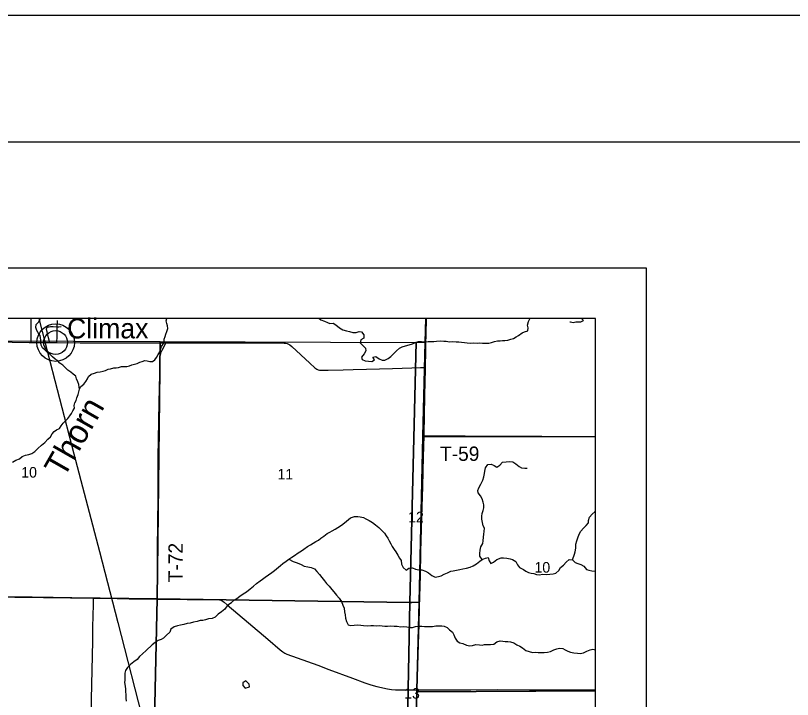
# Model space of a CAD drawing. Extents: x 0 to 34, y 0 to 22.
# Drawn here: x 6.5 to 9.58, y 19.29 to 22 of the extents above; entities that cross this region are included whole.
import ezdxf

# ---------------------------------------------------------------- set-up
doc = ezdxf.new("R2010")
doc.units = 0
for name, color, linetype in [('Default', 7, 'Continuous'), ('GM_X_City_Street', 7, 'Continuous'), ('GM_X_Corporation', 7, 'Continuous'), ('GM_X_County_Road_Text', 7, 'Continuous'), ('GM_X_Interchange_Ramps', 7, 'Continuous'), ('GM_X_Major_River', 7, 'Continuous'), ('GM_X_Major_River_Text', 7, 'Continuous'), ('GM_X_Minor_Lake', 7, 'Continuous'), ('GM_X_Minor_River', 7, 'Continuous'), ('GM_X_Section', 7, 'Continuous'), ('GM_X_Township_Text', 7, 'Continuous'), ('GM_X_Unincorporated_Location', 7, 'Continuous'), ('GM_X_Unincorporated_Text', 7, 'Continuous'), ('SH_Cut_Line', 7, 'Continuous'), ('SH_Data', 7, 'Continuous'), ('SH_Text', 7, 'Continuous')]:
    doc.layers.add(name, color=color, linetype=linetype)

msp = doc.modelspace()

# ---------------------------------------------------------------- linework, layer by layer
at = {"layer": 'Default'}
for points in [[(8.0903, 19.2721), (8.0916, 19.3249), (8.0917, 19.3288), (8.0943, 19.4242), (8.0975, 19.5485), (8.0985, 19.5857), (8.1001, 19.654), (8.1038, 19.7814), (8.1063, 19.8745), (8.111, 20.0547), (8.1134, 20.1323), (8.115, 20.1944), (8.1164, 20.2503), (8.1187, 20.3345), (8.1204, 20.4211), (8.1217, 20.4864), (8.1232, 20.5547), (8.124, 20.5889), (8.1241, 20.6054), (8.1242, 20.623), (8.1249, 20.654), (8.1259, 20.6975), (8.1269, 20.7379), (8.1282, 20.8), (2.9842, 20.8)], [(8.8, 18.8069), (8.8, 20.8), (8.1282, 20.8), (8.1269, 20.7379), (8.1259, 20.6975), (8.1249, 20.654), (8.1242, 20.623), (8.1241, 20.6054), (8.124, 20.5889), (8.1232, 20.5547), (8.1217, 20.4864), (8.1204, 20.4211), (8.1187, 20.3345), (8.1164, 20.2503), (8.115, 20.1944), (8.1134, 20.1323), (8.111, 20.0547), (8.1063, 19.8745), (8.1038, 19.7814), (8.1001, 19.654), (8.0985, 19.5857), (8.0975, 19.5485), (8.0943, 19.4242), (8.0917, 19.3288), (8.0916, 19.3249), (8.0903, 19.2721)]]:
    msp.add_lwpolyline(points, dxfattribs=at)
for points in [[(8.8, 20.3309), (8.8, 20.8), (8.1254, 20.8), (8.1235, 20.706), (8.1135, 20.3325)], [(8.8, 19.3242), (8.8, 20.3309), (8.1135, 20.3325), (8.099, 19.6752), (8.0902, 19.3206)], [(8.8, 18.3267), (8.8, 19.3242), (8.0902, 19.3206), (8.0725, 18.6456), (8.0624, 18.3353)]]:
    msp.add_lwpolyline(points, close=True, dxfattribs=at)
at = {"layer": 'GM_X_City_Street'}
msp.add_line((6.6358, 20.7044), (6.6643, 20.7042), dxfattribs=at)
for points in [[(8.1243, 20.6048), (8.1244, 20.6225), (8.1252, 20.6535), (8.1261, 20.697), (8.1271, 20.7373), (8.1284, 20.8)], [(6.0415, 20.7139), (6.0915, 20.7133), (6.2065, 20.7107), (6.4178, 20.7065), (6.5545, 20.704), (6.5629, 20.7041)], [(6.5629, 20.7041), (6.6135, 20.7045), (6.6358, 20.7044)], [(6.6643, 20.7042), (6.7565, 20.7036), (6.8839, 20.7035), (6.9772, 20.7033), (7.0704, 20.7033), (7.096, 20.7033)], [(7.096, 20.7033), (7.1916, 20.7032), (7.3004, 20.7028), (7.4029, 20.7027), (7.4868, 20.7025), (7.5646, 20.7024), (7.5709, 20.7018), (7.577, 20.7004), (7.5829, 20.698), (7.5883, 20.6947), (7.5956, 20.6887), (7.6663, 20.6231), (7.6869, 20.6043), (7.6944, 20.599), (7.6998, 20.5965), (7.7057, 20.595), (7.7148, 20.5941), (7.7396, 20.5945), (7.7986, 20.5964), (7.8389, 20.5977), (7.8917, 20.599), (7.9942, 20.6018), (8.0719, 20.6042), (8.1061, 20.6049), (8.1154, 20.6049), (8.1243, 20.6048)], [(8.1189, 20.3339), (8.1206, 20.4206), (8.1219, 20.4858), (8.1234, 20.5542), (8.1242, 20.5883), (8.1243, 20.6048)], [(8.0919, 19.3282), (8.0945, 19.4237), (8.0977, 19.5479), (8.0987, 19.5852), (8.1003, 19.6535), (8.1041, 19.7808), (8.1066, 19.874), (8.1112, 20.0541), (8.1136, 20.1317), (8.1152, 20.1939), (8.1166, 20.2498), (8.1189, 20.3339)], [(6.0463, 19.7017), (6.0657, 19.7015), (6.2459, 19.6996), (6.4137, 19.6984), (6.5194, 19.697), (6.5659, 19.6962), (6.6498, 19.6948), (6.7181, 19.6932), (6.8087, 19.6918)], [(6.8087, 19.6918), (6.8548, 19.6909), (6.9511, 19.6892), (7.0101, 19.6884), (7.0625, 19.6878)], [(7.0625, 19.6878), (7.1034, 19.6873), (7.181, 19.6865), (7.2991, 19.6854), (7.3083, 19.6847), (7.3141, 19.6833), (7.3196, 19.6808), (7.3271, 19.6755), (7.3387, 19.6653), (7.4242, 19.5931), (7.5002, 19.529), (7.5498, 19.4865), (7.5595, 19.4787), (7.5675, 19.4737), (7.576, 19.4698), (7.6988, 19.4253), (7.7425, 19.4091), (7.8355, 19.3741), (7.885, 19.3556), (7.9087, 19.3478), (7.9327, 19.3414), (7.9752, 19.3316), (7.9906, 19.3291), (8.0061, 19.328), (8.0496, 19.3278), (8.0919, 19.3282)], [(8.0736, 18.6435), (8.0739, 18.6535), (8.0751, 18.7032), (8.0778, 18.8047), (8.0814, 18.9392), (8.0833, 19.0138), (8.0854, 19.0883), (8.087, 19.1441), (8.0874, 19.1566), (8.0905, 19.2715), (8.0918, 19.3243), (8.0919, 19.3282)], [(8.0919, 19.3282), (8.1033, 19.3282), (8.2276, 19.3285), (8.3052, 19.3286), (8.4109, 19.3288), (8.5382, 19.3286), (8.591, 19.3285), (8.6811, 19.3279), (8.7371, 19.3285), (8.7836, 19.3286), (8.8, 19.3287)]]:
    msp.add_lwpolyline(points, dxfattribs=at)
at = {"layer": 'GM_X_Corporation'}
msp.add_lwpolyline([(6.5927, 20.8), (6.6173, 20.7022), (6.732, 20.2629), (6.8332, 19.8757), (6.9052, 19.5948), (7.0125, 19.1776), (7.1431, 18.6694), (7.2218, 18.3603), (7.335, 17.9018), (7.5012, 17.2442), (7.5672, 16.9911), (7.6376, 16.714), (7.7025, 16.4605), (7.7388, 16.3223), (7.7626, 16.2427), (7.7756, 16.2117), (7.8081, 16.1506), (7.8441, 16.0969), (7.8846, 16.0477), (7.9314, 15.9998), (7.9673, 15.9687)], dxfattribs=at)
at = {"layer": 'GM_X_Interchange_Ramps'}
for points in [[(6.5629, 20.7041), (6.5628, 20.7107), (6.5625, 20.7261), (6.5623, 20.7416), (6.5624, 20.757), (6.5626, 20.7662), (6.5627, 20.7754), (6.5624, 20.7908), (6.5624, 20.8)], [(6.6652, 20.7663), (6.6656, 20.7715), (6.6665, 20.7832), (6.6671, 20.7919)], [(6.6358, 20.7044), (6.6352, 20.7067), (6.6331, 20.7142), (6.6307, 20.7225), (6.6264, 20.7407), (6.6253, 20.7471), (6.6236, 20.7557), (6.6235, 20.7575), (6.6236, 20.7591), (6.6238, 20.7606), (6.6243, 20.7622), (6.626, 20.7645)], [(6.626, 20.7645), (6.6276, 20.7657), (6.6293, 20.7664), (6.6306, 20.7667), (6.6337, 20.7671), (6.6388, 20.7675), (6.6428, 20.7677), (6.6492, 20.7675), (6.6652, 20.7663)], [(6.6643, 20.7042), (6.6644, 20.7066), (6.6651, 20.7254), (6.6651, 20.7317), (6.6648, 20.7467), (6.6649, 20.7558), (6.6652, 20.7663)], [(6.6652, 20.7663), (6.6721, 20.7668), (6.6815, 20.7672)], [(7.0625, 19.6878), (7.0626, 19.6955), (7.0634, 19.8258), (7.0637, 19.8972), (7.0642, 19.9748), (7.0653, 20.102), (7.0663, 20.251), (7.0674, 20.3192), (7.0702, 20.468), (7.0713, 20.5208), (7.0732, 20.6387), (7.0742, 20.6511), (7.076, 20.6602), (7.0779, 20.6661), (7.0818, 20.6745), (7.0909, 20.6907), (7.092, 20.6936), (7.096, 20.7033)], [(8.1189, 20.3339), (8.127, 20.3339), (8.2016, 20.334), (8.2824, 20.334), (8.3352, 20.3338), (8.4253, 20.3334), (8.5434, 20.333), (8.5869, 20.3329), (8.708, 20.3321), (8.8, 20.3317)], [(6.0463, 19.7017), (6.0657, 19.7015), (6.2459, 19.6996), (6.4137, 19.6984), (6.5194, 19.697), (6.5659, 19.6962), (6.6498, 19.6948), (6.7181, 19.6932), (6.8087, 19.6918)], [(6.7887, 18.6761), (6.7888, 18.6826), (6.7928, 18.872), (6.7948, 18.9558), (6.7982, 19.1297), (6.801, 19.2911), (6.8063, 19.5209), (6.8072, 19.5737), (6.8083, 19.6234), (6.8088, 19.6637), (6.8087, 19.6824), (6.8087, 19.6918)], [(6.8087, 19.6918), (6.8548, 19.6909), (6.9511, 19.6892), (7.0101, 19.6884), (7.0625, 19.6878)], [(7.0625, 19.6878), (7.1034, 19.6873), (7.181, 19.6865), (7.2991, 19.6854), (7.3083, 19.6847), (7.3141, 19.6833), (7.3196, 19.6808), (7.3271, 19.6755), (7.3387, 19.6653), (7.4242, 19.5931), (7.5002, 19.529), (7.5498, 19.4865), (7.5595, 19.4787), (7.5675, 19.4737), (7.576, 19.4698), (7.6988, 19.4253), (7.7425, 19.4091), (7.8355, 19.3741), (7.885, 19.3556), (7.9087, 19.3478), (7.9327, 19.3414), (7.9752, 19.3316), (7.9906, 19.3291), (8.0061, 19.328), (8.0496, 19.3278), (8.0919, 19.3282)], [(8.0919, 19.3282), (8.1033, 19.3282), (8.2276, 19.3285), (8.3052, 19.3286), (8.4109, 19.3288), (8.5382, 19.3286), (8.591, 19.3285), (8.6811, 19.3279), (8.7371, 19.3285), (8.7836, 19.3286), (8.8, 19.3287)]]:
    msp.add_lwpolyline(points, dxfattribs=at)
at = {"layer": 'GM_X_Major_River'}
msp.add_line((8.7461, 20.7969), (8.7424, 20.8), dxfattribs=at)
for points in [[(8.6974, 20.7863), (8.6997, 20.7859), (8.7103, 20.7838), (8.7213, 20.7859), (8.7308, 20.7868), (8.7414, 20.7859), (8.7518, 20.7921), (8.7461, 20.7969)], [(7.4059, 19.359), (7.402, 19.3569), (7.402, 19.3451), (7.4104, 19.3344)], [(7.4104, 19.3344), (7.4279, 19.3405), (7.426, 19.3504), (7.4138, 19.3633), (7.4059, 19.359)]]:
    msp.add_lwpolyline(points, dxfattribs=at)
at = {"layer": 'GM_X_Section'}
for points in [[(6.754, 20.5196), (6.752, 20.5276), (6.7511, 20.5383), (6.7473, 20.5491), (6.7426, 20.5598), (6.7399, 20.5705), (6.7291, 20.5792), (6.7192, 20.5874), (6.7073, 20.5954), (6.6973, 20.6059), (6.6873, 20.6149), (6.6762, 20.6224), (6.667, 20.6333), (6.6573, 20.6385), (6.647, 20.6476), (6.637, 20.6566), (6.6266, 20.6645), (6.6174, 20.6742), (6.6074, 20.6836), (6.6024, 20.6933), (6.6008, 20.7028), (6.6011, 20.713), (6.5994, 20.7226), (6.5978, 20.7325), (6.5898, 20.7426), (6.5847, 20.7522), (6.5813, 20.7634), (6.582, 20.7755), (6.591, 20.7855), (6.5977, 20.7967), (6.5989, 20.8)], [(6.6289, 20.3218), (6.6386, 20.3302), (6.645, 20.3418), (6.6528, 20.3519), (6.6628, 20.3581), (6.674, 20.3642), (6.6811, 20.3743), (6.6893, 20.3847), (6.699, 20.3935), (6.708, 20.4035), (6.7151, 20.414), (6.7226, 20.4236), (6.7274, 20.4337), (6.7338, 20.4442), (6.7333, 20.4549), (6.7355, 20.4647), (6.7403, 20.4752), (6.7436, 20.4853), (6.7481, 20.4985), (6.7518, 20.5087), (6.754, 20.5196), (6.7592, 20.5305), (6.7705, 20.5393), (6.7783, 20.5493), (6.785, 20.5598), (6.7891, 20.5699), (6.7996, 20.5791), (6.813, 20.5833), (6.8244, 20.5868), (6.8354, 20.5884), (6.8472, 20.5903), (6.8568, 20.5931), (6.8671, 20.5985), (6.877, 20.6005), (6.8893, 20.604), (6.8991, 20.6041), (6.909, 20.6053), (6.9201, 20.6092), (6.9303, 20.6097), (6.9409, 20.6094), (6.9523, 20.6117), (6.9619, 20.6156), (6.9718, 20.6184), (6.9829, 20.6211), (6.9929, 20.6265), (7.0028, 20.6297), (7.0124, 20.6328), (7.0226, 20.6318), (7.0323, 20.6289), (7.0429, 20.629), (7.0526, 20.6355), (7.0597, 20.6456), (7.0661, 20.6572), (7.0724, 20.6669), (7.0753, 20.6767), (7.079, 20.688), (7.085, 20.6977), (7.0898, 20.7078), (7.0901, 20.7177), (7.093, 20.7278), (7.0959, 20.7376), (7.1004, 20.7485), (7.1041, 20.7598), (7.1033, 20.7701), (7.1005, 20.7801), (7.0978, 20.7904), (7.0995, 20.8)], [(7.7041, 20.8), (7.7107, 20.7947), (7.7251, 20.7889), (7.7364, 20.7835), (7.7467, 20.7796), (7.7588, 20.781), (7.7706, 20.7744), (7.7845, 20.7621), (7.7977, 20.7548), (7.8118, 20.7505), (7.8239, 20.7478), (7.8372, 20.7442), (7.8505, 20.7434), (7.8627, 20.7478), (7.8721, 20.7462), (7.8812, 20.7344), (7.8814, 20.7214), (7.8688, 20.7143), (7.8665, 20.7025), (7.8766, 20.6926), (7.8872, 20.6822), (7.8886, 20.672), (7.882, 20.6591), (7.8717, 20.6459), (7.8739, 20.6364), (7.886, 20.6321), (7.9, 20.6308), (7.9133, 20.6292), (7.9233, 20.6352), (7.9169, 20.6459), (7.9287, 20.6492), (7.9415, 20.6396), (7.954, 20.6349), (7.9639, 20.6348), (7.9773, 20.6408), (7.9887, 20.6487), (7.9995, 20.6608), (8.0102, 20.6717), (8.0228, 20.6822), (8.0328, 20.6875), (8.0465, 20.6915), (8.0606, 20.6948), (8.0735, 20.6997), (8.0857, 20.7041), (8.0983, 20.7082), (8.1101, 20.7089), (8.1234, 20.7076), (8.1359, 20.7079), (8.1485, 20.7078), (8.1583, 20.7088), (8.169, 20.7095), (8.1842, 20.7105), (8.1983, 20.71), (8.2077, 20.7092), (8.2203, 20.7076), (8.2336, 20.7078), (8.2476, 20.7073), (8.2575, 20.7065), (8.2678, 20.7056), (8.2807, 20.704), (8.2905, 20.7035), (8.3053, 20.7023), (8.3164, 20.7029), (8.3304, 20.7021), (8.3403, 20.7027), (8.3509, 20.7019), (8.3623, 20.7014), (8.3768, 20.7017), (8.3867, 20.705), (8.3993, 20.7087), (8.4103, 20.7113), (8.4209, 20.7116), (8.4308, 20.7122)], [(8.4308, 20.7122), (8.4403, 20.7122), (8.4521, 20.7136), (8.4639, 20.7177), (8.4738, 20.7202), (8.4845, 20.727), (8.4945, 20.7326), (8.5082, 20.7431), (8.5181, 20.7461), (8.5311, 20.7509), (8.5331, 20.7623), (8.5294, 20.7737), (8.5333, 20.7878), (8.5391, 20.7984), (8.5397, 20.8)], [(6.4882, 20.2307), (6.5018, 20.2383), (6.5158, 20.2437), (6.5268, 20.2524), (6.5401, 20.2574), (6.5533, 20.2612), (6.5647, 20.2651), (6.5772, 20.2731), (6.5893, 20.2849), (6.6033, 20.2982), (6.6161, 20.3081), (6.6289, 20.3218)], [(8.3506, 19.8447), (8.3407, 19.858), (8.3415, 19.8683), (8.3423, 19.8812), (8.3453, 19.8953), (8.3526, 19.9085), (8.3541, 19.9188), (8.3549, 19.9325), (8.3564, 19.9454), (8.3583, 19.9549), (8.3591, 19.9682), (8.3541, 19.9777), (8.3515, 19.9917), (8.3484, 20.0047), (8.3484, 20.0157), (8.3507, 20.0263), (8.3538, 20.0389), (8.3561, 20.0487), (8.3564, 20.0617), (8.3542, 20.0712), (8.35, 20.0845), (8.3435, 20.0962), (8.3348, 20.1084), (8.3329, 20.1183), (8.3371, 20.1289), (8.3451, 20.1426), (8.3523, 20.1582), (8.3573, 20.1715), (8.3592, 20.1848), (8.3603, 20.1946), (8.3634, 20.2079), (8.3729, 20.2208), (8.3854, 20.222), (8.398, 20.2174), (8.4079, 20.2102), (8.4201, 20.2185), (8.4303, 20.2299), (8.4452, 20.2311), (8.4589, 20.2333), (8.4722, 20.2314), (8.484, 20.2242), (8.4969, 20.2128), (8.5064, 20.2079), (8.519, 20.206), (8.5288, 20.2067)], [(8.7078, 19.8438), (8.7162, 19.8651), (8.7189, 19.8746), (8.7212, 19.8898), (8.7216, 19.9054), (8.7254, 19.9179), (8.7299, 19.9304), (8.7349, 19.9453), (8.741, 19.9567), (8.7516, 19.968), (8.7627, 19.9798), (8.7722, 19.9893), (8.7718, 19.9992), (8.7752, 20.0121), (8.7867, 20.0246), (8.7981, 20.0349), (8.8, 20.0385)], [(7.3416, 19.6651), (7.3558, 19.6745), (7.368, 19.684), (7.3779, 19.6901), (7.39, 19.6988), (7.4026, 19.7083), (7.4163, 19.7166), (7.43, 19.728), (7.4441, 19.7394), (7.4559, 19.7489), (7.4696, 19.7599), (7.4791, 19.7664), (7.4898, 19.7751), (7.5027, 19.7835), (7.516, 19.7934), (7.5263, 19.8013), (7.5506, 19.8203), (7.5605, 19.8283), (7.5735, 19.8385), (7.5837, 19.8454), (7.5955, 19.8537), (7.6058, 19.8609), (7.6207, 19.8708), (7.6336, 19.8788), (7.6431, 19.8849), (7.6583, 19.8955), (7.6694, 19.9027), (7.6796, 19.9092), (7.6911, 19.9156), (7.7009, 19.9209), (7.7108, 19.9293), (7.723, 19.9369), (7.736, 19.9479), (7.7458, 19.9528), (7.7554, 19.9585), (7.7679, 19.9642), (7.7782, 19.9714), (7.7919, 19.9802), (7.8048, 19.9904), (7.8284, 20.0094), (7.8436, 20.0144), (7.8573, 20.0151), (7.8668, 20.014), (7.8794, 20.0105), (7.8893, 20.006), (7.9022, 19.9995), (7.9151, 19.9908), (7.9269, 19.9824), (7.9399, 19.9718), (7.9509, 19.9611), (7.9631, 19.9482), (7.9699, 19.9387), (7.976, 19.9284), (7.9809, 19.9189), (7.9878, 19.906), (7.9938, 19.8961), (8.0014, 19.884), (8.0079, 19.8745), (8.0159, 19.8616), (8.0227, 19.8498), (8.0288, 19.8403), (8.0299, 19.8258), (8.0364, 19.8129), (8.0482, 19.8019), (8.0588, 19.8103), (8.0733, 19.8118), (8.0855, 19.8057), (8.0988, 19.8038), (8.1113, 19.8034), (8.1254, 19.7988), (8.1372, 19.7912), (8.1509, 19.7806), (8.1638, 19.7749), (8.1775, 19.7768), (8.1874, 19.7798), (8.1996, 19.787), (8.2129, 19.7916), (8.2255, 19.7988), (8.2353, 19.7999), (8.262, 19.8045), (8.2734, 19.8079), (8.2886, 19.8102), (8.3019, 19.814), (8.3149, 19.82), (8.3278, 19.8273), (8.3404, 19.8375), (8.3506, 19.8447), (8.3628, 19.85), (8.3742, 19.8523), (8.3784, 19.8386), (8.3841, 19.828), (8.3951, 19.8337), (8.4088, 19.8447), (8.4248, 19.8515), (8.4347, 19.8511), (8.4476, 19.8492), (8.4613, 19.8473), (8.4708, 19.8451), (8.483, 19.8367), (8.4898, 19.8238), (8.4986, 19.8124)], [(7.5837, 19.8454), (7.6005, 19.8363), (7.6126, 19.8328), (7.6229, 19.8286), (7.6328, 19.8245), (7.645, 19.8184), (7.659, 19.815), (7.6724, 19.8123), (7.6857, 19.8077), (7.6944, 19.7975), (7.7047, 19.7845), (7.7142, 19.7728), (7.7256, 19.7598), (7.7332, 19.75), (7.7435, 19.7386), (7.7545, 19.7256), (7.7621, 19.7161), (7.7724, 19.7028), (7.7838, 19.6911), (7.7925, 19.6785), (7.7974, 19.6641), (7.8024, 19.6515), (7.8047, 19.6375), (7.8069, 19.6246), (7.8077, 19.6116), (7.8126, 19.5987), (7.8195, 19.5862), (7.8294, 19.5831), (7.843, 19.5847), (7.8571, 19.585), (7.8697, 19.5839), (7.8792, 19.5827), (7.8967, 19.582), (7.9089, 19.5835), (7.9191, 19.5823), (7.9321, 19.582), (7.9439, 19.5827), (7.9541, 19.5816), (7.9648, 19.5804), (7.9743, 19.5808), (7.9884, 19.5812), (8.0013, 19.5808), (8.0138, 19.5797), (8.0272, 19.5781), (8.0382, 19.5789), (8.0515, 19.5774), (8.0641, 19.5751), (8.0743, 19.5751), (8.0865, 19.5792), (8.0991, 19.5804), (8.1116, 19.58), (8.1211, 19.5792), (8.1329, 19.5785), (8.1432, 19.5785), (8.1538, 19.5796), (8.1664, 19.5811), (8.1767, 19.5815), (8.1896, 19.5819), (8.1991, 19.5807), (8.2113, 19.575), (8.2208, 19.5663), (8.2329, 19.5564), (8.2375, 19.5461), (8.2432, 19.5325), (8.2516, 19.5207), (8.2615, 19.5146), (8.2732, 19.5116), (8.2885, 19.5051), (8.3014, 19.5028), (8.3117, 19.5032), (8.3254, 19.5077), (8.3394, 19.5066), (8.3497, 19.5054), (8.3592, 19.507), (8.3702, 19.507), (8.3832, 19.5081), (8.3965, 19.5092), (8.4083, 19.518), (8.422, 19.5218), (8.4315, 19.5206), (8.4414, 19.5195), (8.4524, 19.5191), (8.4631, 19.5179), (8.476, 19.5141), (8.4882, 19.5065), (8.5, 19.5012), (8.5102, 19.4951), (8.5232, 19.4845), (8.5365, 19.4799), (8.5498, 19.4765), (8.5623, 19.4773), (8.5718, 19.4765), (8.5817, 19.4757), (8.5958, 19.4753), (8.6095, 19.4769), (8.6213, 19.4803), (8.6338, 19.4867), (8.646, 19.4901), (8.6571, 19.4932), (8.67, 19.492), (8.6795, 19.4863)], [(8.4986, 19.8124), (8.5138, 19.8055), (8.5237, 19.7979), (8.5343, 19.7926), (8.545, 19.7903), (8.5549, 19.7884), (8.5651, 19.7846), (8.5769, 19.7835), (8.5899, 19.7865), (8.6039, 19.7846), (8.6188, 19.7861), (8.631, 19.7872), (8.6428, 19.7903), (8.6534, 19.8013), (8.6603, 19.8127), (8.6732, 19.8214), (8.6827, 19.8343), (8.6945, 19.8442), (8.7078, 19.8438), (8.7185, 19.832), (8.7299, 19.8286), (8.7413, 19.8244), (8.7535, 19.8187), (8.7641, 19.8051), (8.7736, 19.8016), (8.7843, 19.8001), (8.7964, 19.7978), (8.8, 19.7977)], [(7.3416, 19.6651), (7.3305, 19.6471), (7.3172, 19.6376), (7.304, 19.6273), (7.2919, 19.6155), (7.2794, 19.6109), (7.2657, 19.609), (7.2528, 19.6059), (7.2434, 19.6032), (7.2327, 19.6021), (7.2199, 19.599), (7.2055, 19.5959), (7.1922, 19.5928), (7.1801, 19.5905), (7.1668, 19.5874), (7.1547, 19.5843), (7.1418, 19.5817), (7.1285, 19.5782), (7.116, 19.5687), (7.1115, 19.5569), (7.0994, 19.5447), (7.0873, 19.5329), (7.0775, 19.5272), (7.0661, 19.5238), (7.0533, 19.5157), (7.0419, 19.5058), (7.0181, 19.4845), (7.0041, 19.4712), (6.9912, 19.4598), (6.9818, 19.4476), (6.9689, 19.4396), (6.9564, 19.4286), (6.9444, 19.416), (6.9364, 19.4042), (6.9342, 19.3947), (6.9335, 19.3815), (6.9339, 19.3667), (6.9328, 19.3568), (6.9344, 19.3432), (6.9359, 19.331), (6.9367, 19.3212), (6.9379, 19.3083), (6.938, 19.2954), (6.9395, 19.2825)], [(8.6795, 19.4863), (8.6894, 19.4814), (8.7008, 19.4776), (8.7133, 19.4742), (8.7282, 19.4734), (8.7388, 19.4726), (8.7521, 19.4749), (8.7651, 19.481), (8.7788, 19.487), (8.7891, 19.4893), (8.8, 19.4867)]]:
    msp.add_lwpolyline(points, dxfattribs=at)
at = {"layer": 'GM_X_Township_Text'}
for radius in [0.0744, 0.0472]:
    msp.add_circle((6.6593, 20.7041), radius, dxfattribs=at)
at = {"layer": 'GM_X_Unincorporated_Location'}
for points in [[(6.0408, 20.7118), (7.074, 20.7079), (7.0617, 19.6888), (6.0459, 19.7005)], [(8.0853, 20.705), (8.0887, 20.7051), (8.0628, 19.6744), (7.0617, 19.6888), (7.074, 20.7079)], [(8.0887, 20.7051), (8.1235, 20.706), (8.1135, 20.3325), (8.099, 19.6752), (8.0709, 19.6746), (8.0628, 19.6744)], [(6.0459, 19.7005), (7.0617, 19.6888), (7.0397, 18.6727), (6.0441, 18.6866)], [(7.0617, 19.6888), (8.0628, 19.6744), (8.0433, 18.6458), (7.0397, 18.6727)], [(8.0628, 19.6744), (8.0709, 19.6746), (8.099, 19.6752), (8.0902, 19.3206), (8.0725, 18.6456), (8.064, 18.6456), (8.0433, 18.6458)]]:
    msp.add_lwpolyline(points, close=True, dxfattribs=at)
at = {"layer": 'GM_X_Unincorporated_Text'}
msp.add_line((6.6593, 20.7041), (6.6593, 20.7041), dxfattribs=at)
at = {"layer": 'SH_Cut_Line'}
for p, q in [((2, 21), (9, 21)), ((9, 21), (9, 14))]:
    msp.add_line(p, q, dxfattribs=at)
at = {"layer": 'SH_Data'}
msp.add_lwpolyline([(1.5, 21.5), (33.5, 21.5), (33.5, 0.5), (1.5, 0.5)], close=True, dxfattribs=at)
at = {"layer": 'SH_Text'}
for points in [[(0, 0), (34, 0), (34, 22), (0, 22)], [(2.9377, 14), (8.8, 14), (8.8, 20.8), (2.9842, 20.8), (2.984, 20.7397), (2.9904, 20.3395), (2.9796, 19.7242), (2.9753, 18.7199), (2.9708, 17.6769), (2.9623, 15.7101), (2.9479, 14.7065)]]:
    msp.add_lwpolyline(points, close=True, dxfattribs=at)

# ---------------------------------------------------------------- texts
at = {"layer": 'GM_X_County_Road_Text'}
for s, rotation, p in [('T-59', 0, (8.1829, 20.2353)), ('T-72', 89.6463, (7.1623, 19.7539))]:
    msp.add_text(s, height=0.05682, rotation=rotation, dxfattribs=at).set_placement(p)
at = {"layer": 'GM_X_Major_River_Text'}
for s, p in [('10', (6.5229, 20.169)), ('11', (7.5387, 20.1615)), ('12', (8.0566, 19.9918)), ('10', (8.5575, 19.7924)), ('13', (8.0408, 19.2932))]:
    msp.add_text(s, height=0.04186, rotation=0, dxfattribs=at).set_placement(p)
at = {"layer": 'GM_X_Minor_Lake'}
msp.add_text('Climax', height=0.07898, rotation=0, dxfattribs=at).set_placement((6.7045, 20.7206))
at = {"layer": 'GM_X_Minor_River'}
msp.add_text('Thorn', height=0.09472, rotation=60.3105, dxfattribs=at).set_placement((6.6919, 20.1641))

doc.saveas('drawing.dxf')
